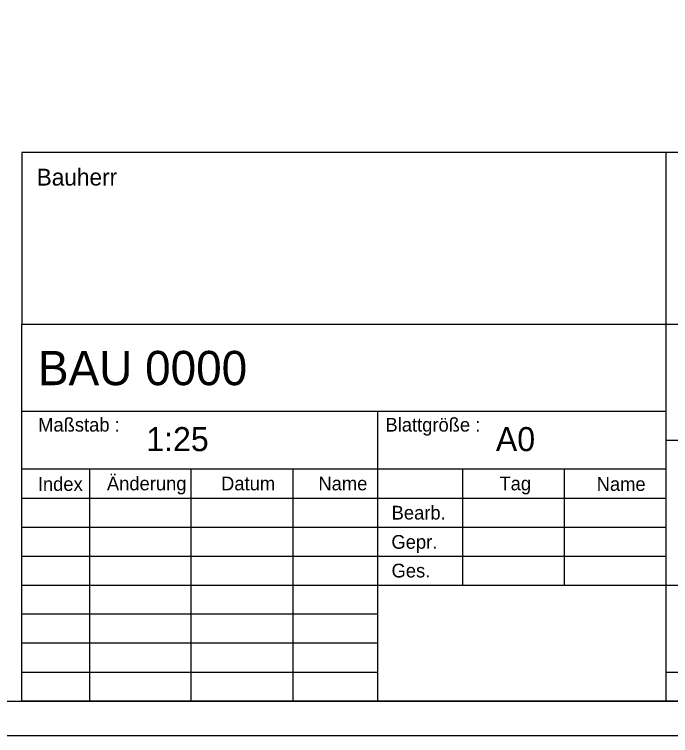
# Model space of a CAD drawing. Extents: x 0 to 29.7, y 0 to 21.
# Drawn here: x 25.127 to 27.516, y 0 to 2.628 of the extents above; entities that cross this region are included whole.
import ezdxf

# ---------------------------------------------------------------- set-up
doc = ezdxf.new("R2010")
doc.units = 0
doc.layers.add('90_Plankopf', color=7, linetype='Continuous')

msp = doc.modelspace()

# ---------------------------------------------------------------- linework, layer by layer
at = {"layer": '90_Plankopf'}
for p, q in [((29.6, 2.1248), (25.153, 2.1248)), ((25.153, 2.1248), (25.153, 1.4998)), ((27.5, 1.4998), (27.5, 2.1248)), ((25.153, 1.4998), (29.6, 1.4998)), ((25.153, 0.125), (25.153, 1.4998)), ((25.153, 1.4998), (29.6, 1.4998)), ((27.5, 0.125), (27.5, 1.4998)), ((25.153, 1.1825), (27.5, 1.1825)), ((26.4501, 0.125), (26.4501, 1.1825)), ((27.5, 1.0768), (29.6, 1.0768)), ((25.153, 0.9718), (27.5, 0.9718)), ((25.4001, 0.971), (25.4001, 0.125)), ((25.7707, 0.125), (25.7707, 0.971)), ((26.1412, 0.125), (26.1412, 0.971)), ((26.7589, 0.971), (26.7589, 0.548)), ((27.1295, 0.548), (27.1295, 0.971)), ((25.153, 0.8658), (27.5, 0.8658)), ((25.153, 0.7595), (27.5, 0.7595)), ((25.153, 0.6538), (27.5, 0.6538)), ((25.153, 0.548), (27.5, 0.548)), ((25.153, 0.548), (27.5, 0.548)), ((26.4501, 0.548), (27.5, 0.548)), ((27.5, 0.548), (29.6, 0.548)), ((26.4501, 0.4423), (25.153, 0.4423)), ((26.4501, 0.3365), (25.153, 0.3365)), ((25.153, 0.2308), (26.4501, 0.2308)), ((27.5, 0.2308), (29.6, 0.2308)), ((29.6, 0.125), (25.153, 0.125)), ((25.153, 0.125), (26.4501, 0.125)), ((25.445, 0.125), (29.6, 0.125)), ((25.445, 0.125), (29.6, 0.125))]:
    msp.add_line(p, q, dxfattribs=at)
for points in [[(0, 0), (29.725, 0), (29.725, 21.025), (0, 21.025)], [(0.625, 0.125), (29.6, 0.125), (29.6, 20.9), (0.625, 20.9)]]:
    msp.add_lwpolyline(points, close=True, dxfattribs=at)

# ---------------------------------------------------------------- texts
for s, height, p in [('Bauherr', 0.06159, (25.2076, 2.0044)), ('BAU 0000      ', 0.125, (25.2123, 1.2769)), ('Maßstab :', 0.05, (25.2129, 1.1079)), ('Blattgröße :', 0.049998, (26.4779, 1.1079)), ('1:25     ', 0.0875, (25.6065, 1.0367)), ('A0       ', 0.0875, (26.88, 1.0367)), ('Änderung', 0.05, (25.4634, 0.8937)), ('Index', 0.05, (25.2117, 0.8918)), ('Datum', 0.05, (25.8792, 0.8937)), ('Name', 0.05, (26.2337, 0.8937)), ('Tag', 0.05, (26.8931, 0.8937)), ('Name', 0.05, (27.2473, 0.8918)), ('Bearb.', 0.05, (26.5004, 0.7873)), ('Gepr.', 0.05, (26.4997, 0.6808)), ('Ges.', 0.05, (26.5001, 0.5762))]:
    msp.add_text(s, height=height, dxfattribs=at).set_placement(p)

doc.saveas('drawing.dxf')
